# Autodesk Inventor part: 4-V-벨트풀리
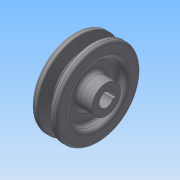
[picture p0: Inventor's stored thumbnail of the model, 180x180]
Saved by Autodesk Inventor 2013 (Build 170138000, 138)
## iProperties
Created: 2015-02
Part Number: 4-V-벨트풀리
Material: 일반
Document SubType Name: Modeling
Designer: Administrator
Density: 1 g/cm^3
Author: Administrator
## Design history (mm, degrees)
sketch "스케치1"
  geometry: L1 (0, 0)-(25, 0); L2 (0, 0)-(0, 11); L3 (0, 11)-(6, 11); L4 (6, 11)-(6, 21.5); L5 (6, 21.5)-(0, 21.5); L6 (0, 21.5)-(0, 32.5); L7 (0, 32.5)-(4.675, 32.5); L8 (4.675, 32.5)-(7.426, 23.5); L9 (7.426, 23.5)-(11.574, 23.5); L10 (11.574, 23.5)-(14.325, 32.5); L11 (14.325, 32.5)-(19, 32.5); L12 (19, 32.5)-(19, 21.5); L13 (19, 21.5)-(13, 21.5); L14 (13, 21.5)-(13, 11); L15 (13, 11)-(25, 11); L16 (25, 11)-(25, 0); 2 further points
  constraints: 32 end point, 8 parallel, 4 horizontal alignment, 4 perpendicular, 3 equal length, 2 point on line, 1 collinear, 1 horizontal, 1 vertical alignment
  dimensions: "d0" = 25 distance of L1.start L1.end; "d1" = 2.7 distance from line of point (5.5, 29.8) L7; "d2" = 6.3 vertical distance of L8.end point (5.5, 29.8); "d4" = 8 distance of point (13.5, 29.8) point (5.5, 29.8); "d5" = 34 deg angle of L10 L8; "d6" = 19 distance between parallel lines of L12 L6; "d7" = 6 distance of L4.end L5.end; "d8" = 65 diameter of L7 L1; "d9" = 43 diameter of L5 L1; "d10" = 22 diameter of L15 L1
revolve "회전1" sketch "스케치1" stored, may be unused: angle "d11" = 90 deg
sketch "스케치2"
  geometry: L1 (-2, 5.123)-(-2, 7.3); L2 (-2, 7.3)-(2, 7.3); L3 (2, 7.3)-(2, 5.123); C1 r 11 at (0, 0) reference; A1 r 5.5 centre (0, 0) between (-2, 5.123) and (2, 5.123)
  constraints: 6 end point, 2 parallel, 2 point on circle, 1 centre point, 1 coincident, 1 perpendicular, 1 vertical
  dimensions: "d12" = 11 diameter of A1; "d14" = 12.8 dimension on A1 L2; "d15" = 4 distance of L1.end L2.end
extrude "돌출1" cut sketch "스케치2" stored distance "d16" = 10; taper "d17" = 0 deg
fillet "모깎기1" dims "d18" = 3, "d19" = 0.5, "d20" = 2, "d21" = 1
node "솔리드1"
